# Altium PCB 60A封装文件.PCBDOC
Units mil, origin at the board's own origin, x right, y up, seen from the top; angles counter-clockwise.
Board outline 660.16 x 530.7 mil, 4 copper layers (Top, Inner Layer 2, Inner Layer 3, Bottom), stack 35.4 mil thick; 1 components, 0 nets, 18 pads, 0 vias.
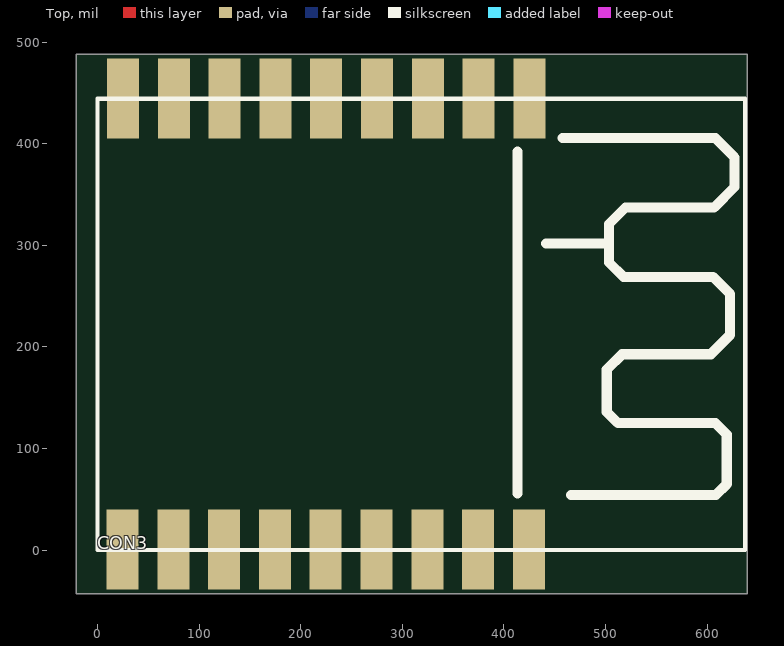
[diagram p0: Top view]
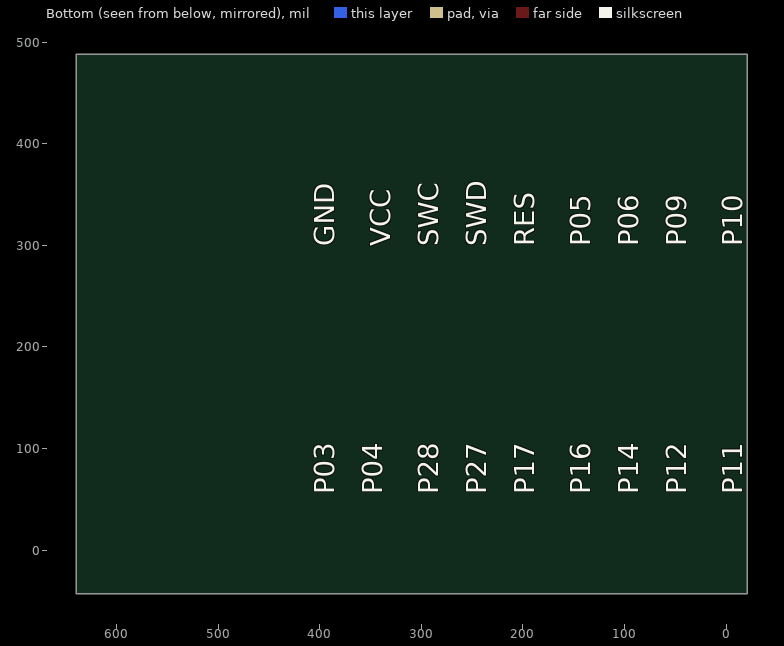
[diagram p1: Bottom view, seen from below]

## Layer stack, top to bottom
Top: signal copper 1.35
Dielectric: dielectric 10, FR-4, Dk 4.3
Inner Layer 2: signal copper 1.35
Dielectric: dielectric 10, FR-4, Dk 4.3
Inner Layer 3: signal copper 1.35
Dielectric: dielectric 10, FR-4, Dk 4.3
Bottom: signal copper 1.35

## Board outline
-20.75,-42.77 639.41,-42.77 639.41,487.94 -20.75,487.94

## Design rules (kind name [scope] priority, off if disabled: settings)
Clearance "'Default' PADS rule_15" [All] p1: gap=5.91
ComponentClearance "'Default' PADS rule_12" [All] p1: gap=0 collisioncheckmode=3 verticalgap=10 showdistances=FALSE
FlightTimeFalling "'Default' PADS rule_6" [All] p1: maximum=10.00
FlightTimeRising "'Default' PADS rule_5" [All] p1: maximum=10.00
Length "'Default' PADS rule" [All] p1: maxlimit=50000 minlimit=0
MatchedLengths "'Default' PADS rule_7" [InNetClass('All Nets')] p1: tolerance=200 checknetsindiffpair=TRUE checkdiffpairvsdiffpair=TRUE checkothers=TRUE
MaxMinImpedance "'Default' PADS rule_4" [All] p1: minimum=50.00 maximum=150.0
ParallelSegment "'Default' PADS rule_3" [All] p1: limit=1000 gap=200
ParallelSegment "'Default' PADS rule_2" [All] p2: limit=1000 gap=200
PlaneClearance "'Class' PADS rule_16" [InNetClass('CLASS_0')] p1: clearance=6
PlaneClearance "'Default' PADS rule_14" [All] p2: clearance=6
PlaneConnect "Power Plane Connect Style - from global settings" [All] p1: planeconnectstyle=Relief reliefexpansion=20 reliefentries=2 reliefconductorwidth=7.87 reliefairgap=10
PolygonConnect [All] p1: connectstyle=Relief reliefconductorwidth=10 reliefentries=4 polygonreliefangle="90 Angle"
RoutingLayers "'Default' PADS rule_10" [All] p1: top layer_v5=TRUE mid layer 1_v5=TRUE mid layer 2_v5=TRUE bottom layer_v5=TRUE
RoutingPriority "'Default' PADS rule_9" [All] p1: routingpriority=3
RoutingTopology "'Default' PADS rule_8" [All] p1: topology=Shortest
RoutingVias "'Default' PADS rule_11" [All] p1: holewidth=5.91 width=11.81 viastyle="Through Hole" minholewidth=5.91 minwidth=11.81 maxholewidth=5.91 maxwidth=11.81
SilkscreenOverComponentPads [All] p1: minsilkscreentomaskgap=10
SolderMaskExpansion "Solder Mask Expansion from CAM settings" [All] p1: expansion=5
Width "'Class' PADS rule" [InNetClass('CLASS_0')] p1: maxlimit=98.43 minlimit=3.94 preferedwidth=7.87
Width "'Default' PADS rule_13" [All] p2: maxlimit=98.43 minlimit=3.94 preferedwidth=7.87
21 further rules are at their usual default settings.

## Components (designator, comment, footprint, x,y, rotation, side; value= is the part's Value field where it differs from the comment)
CON3 "T58A" T58A -0.3,0.71 r0 top

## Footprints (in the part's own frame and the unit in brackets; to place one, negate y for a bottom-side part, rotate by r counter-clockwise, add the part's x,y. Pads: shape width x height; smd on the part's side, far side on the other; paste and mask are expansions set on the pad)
T58A [mm]
  rect 0.8x2 smd: 1(10.807,11.274) 2(9.537,11.274) 3(8.267,11.274) 4(6.997,11.274) 5(5.727,11.274) 6(4.457,11.274) 7(3.187,11.274) 8(1.917,11.274) 9(0.647,11.274) 10(0.634,-0.003) 11(1.904,-0.003) 12(3.174,-0.003) 13(4.444,-0.003) 14(5.714,-0.003) 15(6.984,-0.003) 16(8.254,-0.003) 17(9.524,-0.003) 18(10.794,-0.003)
  silkscreen extent 0.01,-0.01 16.2,11.27

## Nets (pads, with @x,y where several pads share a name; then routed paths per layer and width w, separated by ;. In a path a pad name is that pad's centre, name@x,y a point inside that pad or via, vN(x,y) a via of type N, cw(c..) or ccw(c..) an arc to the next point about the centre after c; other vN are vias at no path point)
pads on no net: CON3.1 CON3.2 CON3.3 CON3.4 CON3.5 CON3.6 CON3.7 CON3.8 CON3.9 CON3.10 CON3.11 CON3.12 CON3.13 CON3.14 CON3.15 CON3.16 CON3.17 CON3.18

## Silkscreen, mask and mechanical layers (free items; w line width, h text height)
Silkscreen Bottom:
  text "P10" at -15.75,299.21 h19.68 r270
  text "P09" at 39.37,299.21 h19.68 r270
  text "P06" at 86.61,299.21 h19.68 r270
  text "P05" at 133.86,299.21 h19.68 r270
  text "RES" at 188.98,299.21 h19.68 r270
  text "SWD" at 236.22,299.21 h19.68 r270
  text "SWC" at 283.46,299.21 h19.68 r270
  text "VCC" at 330.71,299.21 h19.68 r270
  text "GND" at 385.83,299.21 h19.68 r270
  text "P11" at -15.75,55.12 h19.68 r270
  text "P12" at 39.37,55.12 h19.68 r270
  text "P14" at 86.61,55.12 h19.68 r270
  text "P16" at 133.86,55.12 h19.68 r270
  text "P17" at 188.98,55.12 h19.68 r270
  text "P27" at 236.22,55.12 h19.68 r270
  text "P28" at 283.46,55.12 h19.68 r270
  text "P04" at 338.58,55.12 h19.68 r270
  text "P03" at 385.83,55.12 h19.68 r270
